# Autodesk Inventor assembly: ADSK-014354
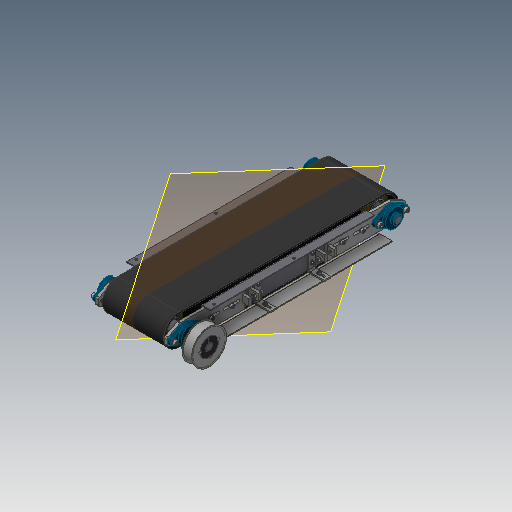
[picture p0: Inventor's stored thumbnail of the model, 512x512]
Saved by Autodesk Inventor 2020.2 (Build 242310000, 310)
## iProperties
Created: 2019-10
Part Number: ADSK-014354
Document SubType Name: Assembly
Designer: lutzd
Mass: 46398 g
Surface Area: 24115.2 cm^2
Volume: 7560.38 cm^3
Density: 6.137 g/cm^3
VLDS_Profile: Default Assembly
VLDS_TimeStamp: 2016-07-29
VLDS_FailCnt: 0
VLDS_AcceptCnt: 0
Dimensions: 935,4x740,5x415,8 mm
Mass: 46,398 kg
DocNumber: ADSK-014354
Folder: 01 - Themengebiete\Simplification\01 - Packaging machine\
Original: C:\AB_Vault\CAD\01 - Themengebiete\Simplification\01 - Packaging machine\ADSK-014353.iam
VDS_Category: 3D Komponenten
VDS_NumSchm: Autodesk
Title: belt conveyor
Author: lutzd
Revision Number: -
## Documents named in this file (23)
- D:\07 - DEMODATEN\OTX 2019 - Dataset - UPDATE - Dez2019\Designs\07-Packing machine\ADSK-014354.iam
- D:\07 - DEMODATEN\OTX 2019 - Dataset - UPDATE - Dez2019\Designs\07-Packing machine\500467R.iam
- D:\07 - DEMODATEN\OTX 2019 - Dataset - UPDATE - Dez2019\Designs\07-Packing machine\500533.iam
- D:\07 - DEMODATEN\OTX 2019 - Dataset - UPDATE - Dez2019\Designs\07-Packing machine\Parts\ADSK-011789.ipt
- D:\07 - DEMODATEN\OTX 2019 - Dataset - UPDATE - Dez2019\Designs\07-Packing machine\Parts\ADSK-011476.ipt
- D:\07 - DEMODATEN\OTX 2019 - Dataset - UPDATE - Dez2019\Designs\07-Packing machine\Parts\ADSK-011712.ipt
- D:\07 - DEMODATEN\OTX 2019 - Dataset - UPDATE - Dez2019\Designs\07-Packing machine\Parts\ADSK-011477.ipt
- D:\07 - DEMODATEN\OTX 2019 - Dataset - UPDATE - Dez2019\Designs\07-Packing machine\Parts\ADSK-011840.ipt
- D:\07 - DEMODATEN\OTX 2019 - Dataset - UPDATE - Dez2019\Designs\07-Packing machine\Parts\ADSK-014338.ipt
- D:\07 - DEMODATEN\OTX 2019 - Dataset - UPDATE - Dez2019\Content Center Files\de-DE\DIN 125-1  B\DIN 125-1 - B 6,4.ipt
- D:\07 - DEMODATEN\OTX 2019 - Dataset - UPDATE - Dez2019\Content Center Files\de-DE\ISO 4032(1)\ISO 4032 - M6DIN EN.ipt
- D:\07 - DEMODATEN\OTX 2019 - Dataset - UPDATE - Dez2019\Content Center Files\de-DE\ISO 4762(2)\ISO 4762 - M6 x 20ISO.ipt
- D:\07 - DEMODATEN\OTX 2019 - Dataset - UPDATE - Dez2019\Content Center Files\de-DE\DIN 125-1  B\DIN 125-1 - B 8,4.ipt
- D:\07 - DEMODATEN\OTX 2019 - Dataset - UPDATE - Dez2019\Content Center Files\de-DE\ISO 4032(1)\ISO 4032 - M8DIN EN.ipt
- D:\07 - DEMODATEN\OTX 2019 - Dataset - UPDATE - Dez2019\Content Center Files\de-DE\ISO 4762(2)\ISO 4762 - M8 x 25ISO.ipt
- D:\07 - DEMODATEN\OTX 2019 - Dataset - UPDATE - Dez2019\Content Center Files\de-DE\ISO 4762(2)\ISO 4762 - M8 x 45ISO.ipt
- D:\07 - DEMODATEN\OTX 2019 - Dataset - UPDATE - Dez2019\Content Center Files\de-DE\DIN 125-1  B\DIN 125-1 - B 10,5.ipt
- D:\07 - DEMODATEN\OTX 2019 - Dataset - UPDATE - Dez2019\Content Center Files\de-DE\ISO 4762(2)\ISO 4762 - M10 x 25ISO.ipt
- D:\07 - DEMODATEN\OTX 2019 - Dataset - UPDATE - Dez2019\Content Center Files\de-DE\DIN 471(2)\DIN 471 - 52 x 2(1).ipt
- D:\07 - DEMODATEN\OTX 2019 - Dataset - UPDATE - Dez2019\Content Center Files\de-DE\ISO 2491 - A\ISO 2491 - A  6 x 4 x 36.ipt
- D:\07 - DEMODATEN\OTX 2019 - Dataset - UPDATE - Dez2019\Designs\07-Packing machine\ADSK-014342.iam
- D:\07 - DEMODATEN\OTX 2019 - Dataset - UPDATE - Dez2019\Designs\07-Packing machine\Parts\ADSK-014366.ipt
- D:\07 - DEMODATEN\OTX 2019 - Dataset - UPDATE - Dez2019\Designs\07-Packing machine\Parts\ADSK-014507.ipt
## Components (136 placed, 22 different names)
1. 500467R:1 [sub-assembly]
2. 500533:1 [sub-assembly]
3. ADSK-011789:1
4. ADSK-011476:1
5. ADSK-011712:1
6. 500533:2 [sub-assembly]
7. ADSK-011712:2
8. 500533:3 [sub-assembly]
9. 500533:4 [sub-assembly]
10. ADSK-011477:1
11. ADSK-011712:3
12. ADSK-011712:4
13. ADSK-011789:2
14. ADSK-011789:3
15. ADSK-011789:4
16. ADSK-011840:1
17. ADSK-014338:1 — Passend:184, Passend:186, Passend:188
18. ADSK-014338:2 — Passend:165, Passend:173
19. ADSK-014338:3 — Passend:169, Passend:171
20. ADSK-014338:4 — Passend:167, Fluchtend:170
21. ADSK-014342:1 [sub-assembly]
22. ADSK-014366:1 — Passend:165, Passend:166
23. ADSK-014507:1 — Fluchtend:169, Passend:167, Fluchtend:170
24. DIN 125-1 B B 6,4:24 — Passend:184, Einfügen:54
25. DIN 125-1 B B 6,4:25
26. DIN 125-1 B B 6,4:26
27. DIN 125-1 B B 6,4:27 — Passend:186, Einfügen:55
28. DIN EN 24032 M6:13
29. DIN EN 24032 M6:14
30. ISO 4762 M6 x 20:13 — Einfügen:54
31. ISO 4762 M6 x 20:14 — Einfügen:55
32. DIN 125-1 B B 6,4:28
33. DIN 125-1 B B 6,4:29 — Passend:188
34. DIN EN 24032 M6:15
35. ISO 4762 M6 x 20:15
36. DIN 125-1 B B 6,4:17
37. DIN 125-1 B B 6,4:18 — Passend:177, Passend:179
38. DIN 125-1 B B 6,4:19 — Passend:169
39. DIN 125-1 B B 6,4:20 — Passend:171
40. DIN 125-1 B B 6,4:21
41. DIN 125-1 B B 6,4:23 — Passend:173
42. DIN EN 24032 M6:9
43. DIN EN 24032 M6:11
44. DIN EN 24032 M6:12
45. ISO 4762 M6 x 20:9 — Passend:177
46. ISO 4762 M6 x 20:10 — Passend:179
47. ISO 4762 M6 x 20:12
48. DIN 125-1 B B 6,4:2
49. DIN 125-1 B B 6,4:4
50. DIN 125-1 B B 6,4:6
51. DIN 125-1 B B 6,4:8
52. DIN 125-1 B B 6,4:9
53. DIN 125-1 B B 6,4:10
54. DIN 125-1 B B 6,4:11
55. DIN 125-1 B B 6,4:12
56. DIN 125-1 B B 6,4:13
57. DIN 125-1 B B 6,4:14
58. DIN 125-1 B B 6,4:15
59. DIN 125-1 B B 6,4:16
60. DIN EN 24032 M6:1
61. DIN EN 24032 M6:2
62. DIN EN 24032 M6:3
63. DIN EN 24032 M6:4
64. DIN EN 24032 M6:7
65. DIN EN 24032 M6:8
66. ISO 4762 M6 x 20:1
67. ISO 4762 M6 x 20:4
68. ISO 4762 M6 x 20:5
69. ISO 4762 M6 x 20:6
70. ISO 4762 M6 x 20:7
71. ISO 4762 M6 x 20:8
72. DIN 125-1 B B 8,4:1
73. DIN 125-1 B B 8,4:2
74. DIN 125-1 B B 8,4:3
75. DIN 125-1 B B 8,4:4
76. DIN 125-1 B B 8,4:5
77. DIN 125-1 B B 8,4:6
78. DIN 125-1 B B 8,4:7
79. DIN 125-1 B B 8,4:8
80. DIN 125-1 B B 8,4:9
81. DIN 125-1 B B 8,4:10
82. DIN 125-1 B B 8,4:11
83. DIN 125-1 B B 8,4:12
84. DIN 125-1 B B 8,4:13
85. DIN 125-1 B B 8,4:14
86. DIN 125-1 B B 8,4:15
87. DIN 125-1 B B 8,4:16
88. DIN EN 24032 M8:1
89. DIN EN 24032 M8:2
90. DIN EN 24032 M8:3
91. DIN EN 24032 M8:4
92. DIN EN 24032 M8:5
93. DIN EN 24032 M8:6
94. DIN EN 24032 M8:7
95. DIN EN 24032 M8:8
96. ISO 4762 M8 x 25:1
97. ISO 4762 M8 x 25:2
98. ISO 4762 M8 x 25:3
99. ISO 4762 M8 x 25:4
100. ISO 4762 M8 x 25:5
101. ISO 4762 M8 x 25:6
102. ISO 4762 M8 x 25:7
103. ISO 4762 M8 x 25:8
104. ISO 4762 M8 x 45:1
105. ISO 4762 M8 x 45:2
106. ISO 4762 M8 x 45:3
107. ISO 4762 M8 x 45:4
108. DIN EN 24032 M8:9
109. DIN EN 24032 M8:10
110. DIN EN 24032 M8:11
111. DIN EN 24032 M8:12
112. DIN 125-1 B B 10,5:1
113. DIN 125-1 B B 10,5:2
114. DIN 125-1 B B 10,5:3
115. DIN 125-1 B B 10,5:4
116. DIN 125-1 B B 10,5:5
117. DIN 125-1 B B 10,5:6
118. DIN 125-1 B B 10,5:7
119. DIN 125-1 B B 10,5:8
120. ISO 4762 M10 x 25:1
121. ISO 4762 M10 x 25:2
122. ISO 4762 M10 x 25:3
123. ISO 4762 M10 x 25:4
124. ISO 4762 M10 x 25:5
125. ISO 4762 M10 x 25:6
126. ISO 4762 M10 x 25:7
127. ISO 4762 M10 x 25:8
128. DIN 471 > 9mm <= 300mm 52 x 2:1
129. DIN 471 > 9mm <= 300mm 52 x 2:2
130. DIN 471 > 9mm <= 300mm 52 x 2:3
131. DIN 471 > 9mm <= 300mm 52 x 2:4
132. DIN 471 > 9mm <= 300mm 52 x 2:5
133. DIN 471 > 9mm <= 300mm 52 x 2:6
134. DIN 471 > 9mm <= 300mm 52 x 2:7
135. DIN 471 > 9mm <= 300mm 52 x 2:8
136. ISO 2491 A A  6 x 4 x 36:1
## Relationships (15: Mate 11, Flush 2, Insert 2)
- Passend:165 [Mate]: ADSK-014338:2 ↔ ADSK-014366:1
- Passend:166 [Mate]: ADSK-014366:1
- Fluchtend:169 [Flush]: ADSK-014507:1
- Passend:167 [Mate]: ADSK-014338:4 ↔ ADSK-014507:1
- Fluchtend:170 [Flush]: ADSK-014338:4 ↔ ADSK-014507:1
- Passend:169 [Mate]: ADSK-014338:3 ↔ DIN 125-1 B B 6,4:19
- Passend:171 [Mate]: ADSK-014338:3 ↔ DIN 125-1 B B 6,4:20
- Passend:173 [Mate]: ADSK-014338:2 ↔ DIN 125-1 B B 6,4:23
- Passend:177 [Mate]: DIN 125-1 B B 6,4:18 ↔ ISO 4762 M6 x 20:9
- Passend:179 [Mate]: DIN 125-1 B B 6,4:18 ↔ ISO 4762 M6 x 20:10
- Passend:184 [Mate]: ADSK-014338:1 ↔ DIN 125-1 B B 6,4:24
- Passend:186 [Mate]: ADSK-014338:1 ↔ DIN 125-1 B B 6,4:27
- Einfügen:54 [Insert]: DIN 125-1 B B 6,4:24 ↔ ISO 4762 M6 x 20:13
- Einfügen:55 [Insert]: DIN 125-1 B B 6,4:27 ↔ ISO 4762 M6 x 20:14
- Passend:188 [Mate]: ADSK-014338:1 ↔ DIN 125-1 B B 6,4:29
